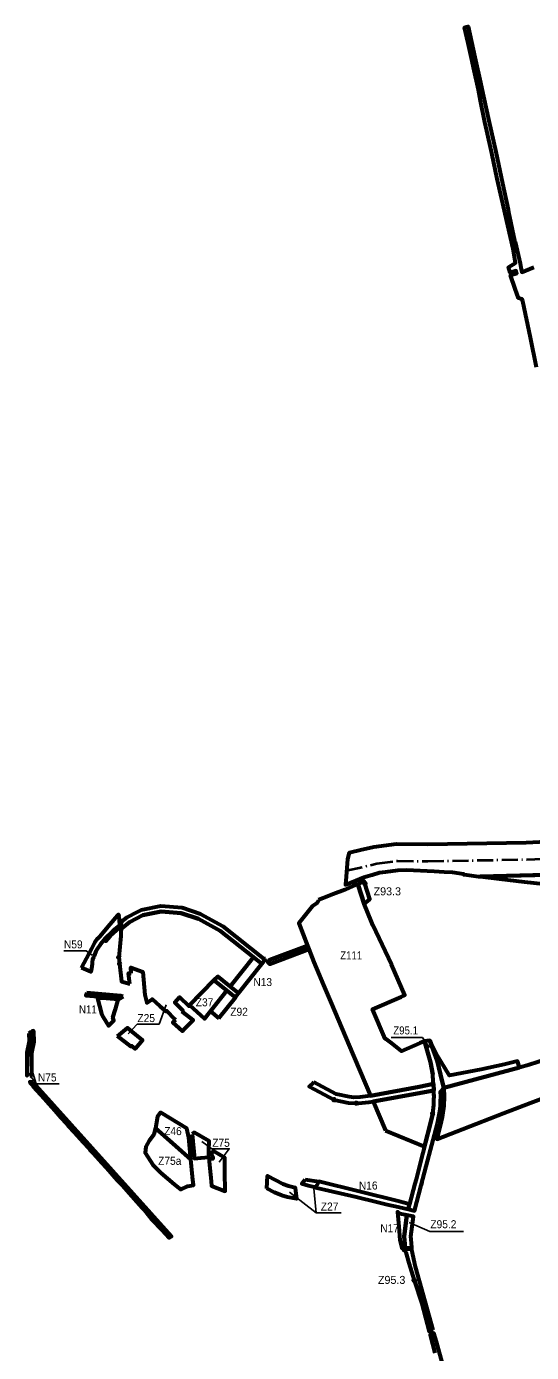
# Model space of a CAD drawing. Extents: x -650277 to -643422, y -1073980 to -1066720.
# Drawn here: x -650277 to -648765, y -1070696 to -1066720 of the extents above; entities that cross this region are included whole.
import ezdxf

# ---------------------------------------------------------------- set-up
doc = ezdxf.new("R2010")
doc.units = 0
doc.header["$LTSCALE"] = 9.6
doc.header["$PDMODE"] = 32
doc.header["$PDSIZE"] = 4.8
doc.linetypes.add('DOT_DASHED', pattern=[7.7, 5, -1.2, 0.3, -1.2])
for name, color, linetype, lineweight in [('1', 7, 'Continuous', 60), ('11', 7, 'Continuous', 60), ('12', 7, 'Continuous', 60), ('13', 7, 'Continuous', 60), ('15', 7, 'Continuous', 60), ('18', 7, 'Continuous', 60), ('24', 7, 'Continuous', 60), ('3', 7, 'Continuous', 60), ('40', 7, 'Continuous', 60), ('41', 7, 'Continuous', 60), ('42', 7, 'Continuous', 60), ('48', 7, 'Continuous', 60), ('60', 7, 'Continuous', 60), ('62', 7, 'DOT_DASHED', 40), ('63', 7, 'Continuous', 25), ('7', 7, 'Continuous', 60), ('9', 7, 'Continuous', 60)]:
    doc.layers.add(name, color=color, linetype=linetype, lineweight=lineweight)

msp = doc.modelspace()

# ---------------------------------------------------------------- linework, layer by layer
at = {"layer": '1'}
msp.add_line((-650000.59, -1069511.15), (-649998.5, -1069529.88), dxfattribs=at)
for points in [[(-649814.067, -1069377.972), (-649874.391, -1069373.859), (-649929.015, -1069384.784), (-649968.465, -1069405.189)], [(-649598.004, -1069510.814), (-649697.525, -1069431.522), (-649762.488, -1069395.854), (-649814.067, -1069377.972)], [(-649968.465, -1069405.189), (-649994.293, -1069425.949), (-649994.53, -1069447.61), (-650000.59, -1069511.15), (-650000.59, -1069511.15)], [(-649812.153, -1069672.884), (-649809.47, -1069670.13), (-649833.38, -1069646.08), (-649818.71, -1069630.64), (-649791.3, -1069657.21), (-649788.91, -1069654.4), (-649715.908, -1069579.804), (-649704.646, -1069568.296), (-649688.446, -1069581.203), (-649667.188, -1069598.14), (-649598.004, -1069510.814)], [(-649998.5, -1069529.88), (-649992.59, -1069582.88), (-649967.81, -1069590.74)], [(-649963.43, -1069557.91), (-649965.26, -1069541.51), (-649928.48, -1069554.57), (-649923.17, -1069623.14)], [(-649967.81, -1069590.74), (-649971.38, -1069558.79), (-649963.43, -1069557.91)], [(-649923.17, -1069623.14), (-649918.35, -1069643.45), (-649917.38, -1069647.56), (-649900.64, -1069636.78), (-649877.82, -1069656.83), (-649864.596, -1069668.455), (-649859.96, -1069672.53)], [(-649859.96, -1069672.53), (-649859.17, -1069673.22), (-649857.49, -1069671.46), (-649833.94, -1069695.24), (-649831.124, -1069698.083)], [(-649831.124, -1069698.083), (-649838.99, -1069706.15), (-649819.9, -1069723.61), (-649810.41, -1069732.28), (-649807.66, -1069729.46), (-649792.13, -1069713.65), (-649777.94, -1069699.2), (-649808.96, -1069675.34), (-649812.153, -1069672.884)]]:
    msp.add_lwpolyline(points, dxfattribs=at)
at = {"layer": '1', "lineweight": 25}
msp.add_lwpolyline([(-649946, -1069711), (-649880, -1069711), (-649859, -1069653)], dxfattribs=at)
at = {"layer": '1'}
for points in [[(-650004.59, -1069747.27), (-649974.86, -1069721.96), (-649966.52, -1069728.87), (-649929.38, -1069759.65), (-649951.56, -1069785.42), (-649963, -1069776.7), (-649965, -1069778.7)], [(-649557.21, -1070203.53), (-649555.44, -1070165.91), (-649532.57, -1070178.08), (-649509.72, -1070190.24), (-649492.67, -1070196.34), (-649472.6, -1070201.15), (-649472.43, -1070202.9), (-649469.176, -1070235.365), (-649496, -1070230), (-649513, -1070225), (-649535, -1070216)], [(-649442.63, -1070176.69), (-649402.29, -1070182.92), (-649404.2, -1070187.43), (-649412.2, -1070200.71), (-649433.3, -1070195.89), (-649453.27, -1070190.02), (-649446.19, -1070180.76)]]:
    msp.add_lwpolyline(points, close=True, dxfattribs=at)
for p in [(-650000.59, -1069511.15), (-649998.5, -1069529.88)]:
    msp.add_point(p, dxfattribs=at)
at = {"layer": '11'}
msp.add_lwpolyline([(-649788.91, -1069654.4), (-649744.517, -1069695.746), (-649677.124, -1069610.681), (-649715.908, -1069579.804)], close=True, dxfattribs=at)
at = {"layer": '12'}
for points in [[(-649891.21, -1070022.68), (-649832.007, -1070074.751), (-649784.87, -1070116.76), (-649791.31, -1070051.51), (-649797.45, -1070023.77), (-649876.31, -1069975.93), (-649884.59, -1069988.57)], [(-649891.21, -1070022.68), (-649895.45, -1070042.15), (-649910.34, -1070061.29), (-649919.55, -1070079.01), (-649922.3, -1070096.9), (-649898.55, -1070132.9), (-649874.94, -1070157.19), (-649835.28, -1070191.27), (-649815.33, -1070206.63), (-649794.37, -1070197.2), (-649777.29, -1070193.57), (-649779.75, -1070168.69), (-649784.87, -1070116.76)]]:
    msp.add_lwpolyline(points, close=True, dxfattribs=at)
at = {"layer": '13'}
msp.add_line((-649202.375, -1070030.469), (-649085.737, -1070078.201), dxfattribs=at)
for points in [[(-649057.868, -1069910.51), (-649239.635, -1069943.094), (-649202.375, -1070030.469)], [(-649085.737, -1070078.201), (-649066.487, -1070004.267), (-649061.139, -1069979.254), (-649061.138, -1069979.243)]]:
    msp.add_lwpolyline(points, dxfattribs=at)
msp.add_arc((-649347.129, -1069931.193), 290, 350.46253, 4.08974, dxfattribs=at)
msp.add_point((-649061.138, -1069979.243), dxfattribs=at)
at = {"layer": '15'}
msp.add_line((-649057.868, -1069910.51), (-649058.82, -1069890.548), dxfattribs=at)
for points in [[(-648749.97, -1067741.49), (-648767.84, -1067652.98), (-648791.68, -1067543.78), (-648792.97, -1067537.86), (-648804.08, -1067534.88), (-648813.94, -1067506.27), (-648827.86, -1067465.86), (-648809.65, -1067459.77), (-648809.97, -1067458.52), (-648811.21, -1067453.52), (-648811.4, -1067452.79), (-648829.54, -1067458.42), (-648834.01, -1067441.81), (-648812.91, -1067429.16), (-648820.39, -1067386.83), (-648844.16, -1067281.37), (-648845.94, -1067272.85), (-648867.82, -1067176.66), (-648884.26, -1067099.63), (-648899.1, -1067033.34), (-648905.06, -1067006.7), (-648917.76, -1066942.65), (-648924.32, -1066909.55), (-648936.7, -1066852.52), (-648944.75, -1066815.41), (-648955.15, -1066770.11), (-648965.39, -1066723.15), (-648959.88, -1066721.59), (-648954.86, -1066720.16), (-648935.19, -1066812.53), (-648918.27, -1066888.41), (-648914.11, -1066907.05), (-648893.02, -1067002.5), (-648872.31, -1067095.5), (-648851.87, -1067191.04), (-648835.29, -1067268.93), (-648833.66, -1067276.77), (-648816.06, -1067361.71), (-648813.81, -1067365.91), (-648799.58, -1067430.4), (-648796.8, -1067443.1), (-648795.88, -1067447.21), (-648794.7, -1067452.46), (-648793.71, -1067456.88), (-648757.97, -1067441.51)], [(-649561.17, -1069515.83), (-649566.951, -1069515.099), (-649688.625, -1069418.156), (-649755.971, -1069381.179), (-649810.846, -1069362.154), (-649875.434, -1069357.751), (-649934.363, -1069369.537), (-649945.397, -1069375.277), (-649977.239, -1069391.714), (-649994.329, -1069405.451)], [(-649994.293, -1069425.949), (-649968.465, -1069405.189), (-649929.015, -1069384.784), (-649874.391, -1069373.859)], [(-649874.391, -1069373.859), (-649814.067, -1069377.972), (-649762.488, -1069395.854), (-649697.525, -1069431.522), (-649598.004, -1069510.814), (-649572.972, -1069530.758)], [(-649994.329, -1069405.451), (-649994.329, -1069405.451), (-649994.293, -1069425.949), (-649994.293, -1069425.949)], [(-649572.972, -1069530.758), (-649561.91, -1069516.78), (-649561.17, -1069515.83)], [(-650096.627, -1069617.746), (-650099.55, -1069625.53), (-650002.39, -1069633.65)], [(-649987.49, -1069628.6), (-649994.913, -1069626.246), (-650096.627, -1069617.746)], [(-650002.39, -1069633.65), (-650002.65, -1069637.14), (-649987.49, -1069628.6)], [(-649417.234, -1069885.193), (-649418.94, -1069887.36), (-649430.515, -1069898.514), (-649356.458, -1069937.945)], [(-649246.81, -1069926.27), (-649278.492, -1069930.573), (-649296.851, -1069931.092), (-649310.738, -1069929.342), (-649350.222, -1069920.873), (-649417.234, -1069885.193)], [(-649058.82, -1069890.548), (-649101.89, -1069898.73), (-649246.81, -1069926.27)], [(-649356.458, -1069937.945), (-649312.646, -1069947.342), (-649289.95, -1069948.146)], [(-649289.95, -1069948.146), (-649282.437, -1069948.342), (-649251.805, -1069945.276), (-649239.635, -1069943.094), (-649057.868, -1069910.51)]]:
    msp.add_lwpolyline(points, dxfattribs=at)
for points in [[(-650025.31, -1069446.49), (-649998.512, -1069422.926), (-649999.01, -1069415.628), (-650018.873, -1069431.749), (-650043.521, -1069455.69), (-650045.72, -1069459.1), (-650040.012, -1069461.999)], [(-649547.733, -1069530.185), (-649431.761, -1069486.57), (-649435.578, -1069476.772), (-649550.53, -1069519.68), (-649554.83, -1069525), (-649551.32, -1069528.49), (-649549.69, -1069530.14), (-649548.881, -1069530.963)], [(-649677.124, -1069610.681), (-649651.846, -1069630.82), (-649641.978, -1069618.226), (-649667.188, -1069598.14), (-649688.446, -1069581.203), (-649704.646, -1069568.296), (-649715.908, -1069579.804)], [(-648800.85, -1069841.52), (-648806.946, -1069821.79), (-648846.924, -1069832.58), (-648916.03, -1069847.12), (-649010.55, -1069865.09), (-649049.22, -1069801.23), (-649069.4, -1069760.67), (-649048, -1069820), (-649032.928, -1069882.782), (-649028.017, -1069902.109)]]:
    msp.add_lwpolyline(points, close=True, dxfattribs=at)
for p in [(-649994.329, -1069405.451), (-649994.293, -1069425.949), (-649356.458, -1069937.945), (-649289.95, -1069948.146)]:
    msp.add_point(p, dxfattribs=at)
at = {"layer": '18'}
for points in [[(-649781.53, -1070041.2), (-649774.45, -1070113.92), (-649754.82, -1070111.89), (-649731.12, -1070109.96), (-649730.96, -1070094.91), (-649730.89, -1070088.96), (-649730.6, -1070061.98), (-649774.73, -1070035.58)], [(-649730.57, -1070115.76), (-649730, -1070122.01), (-649726.22, -1070162.75), (-649725.49, -1070170.64), (-649723.17, -1070195.81), (-649682.04, -1070211.58), (-649683.12, -1070154.14), (-649682.98, -1070132.1), (-649683.57, -1070112.05), (-649717.72, -1070091.61), (-649718.71, -1070093.35), (-649724.36, -1070099.03), (-649719.69, -1070108.94), (-649719.24, -1070114.87)]]:
    msp.add_lwpolyline(points, close=True, dxfattribs=at)
at = {"layer": '24'}
for points in [[(-649321.69, -1069307.61), (-649324.3, -1069308.59), (-649359.48, -1069321.82), (-649389.4, -1069333.35), (-649396.52, -1069336.09), (-649403.92, -1069338.26)], [(-649283.702, -1069294.132), (-649284.695, -1069291.033), (-649300.133, -1069297.95), (-649321.69, -1069307.61)], [(-649060.897, -1069861.994), (-649068, -1069825.147), (-649085.41, -1069762.44), (-649085.41, -1069762.44), (-649099.75, -1069768.575), (-649154.76, -1069792.11), (-649184.05, -1069768.45), (-649200.64, -1069756.53), (-649202.99, -1069754.99), (-649241.11, -1069665.9), (-649155.082, -1069629.097), (-649144.57, -1069624.6), (-649184.1, -1069532.2), (-649240.202, -1069414.528), (-649244.08, -1069404.753), (-649265.774, -1069350.068), (-649283.702, -1069294.132)], [(-649403.92, -1069338.26), (-649403.03, -1069340.66), (-649408.81, -1069349.89), (-649422.19, -1069357.99), (-649462.25, -1069408.32), (-649435.578, -1069476.772), (-649431.761, -1069486.57)], [(-649431.761, -1069486.57), (-649416.52, -1069525.68), (-649409.355, -1069544.517), (-649388.438, -1069594.296), (-649379.32, -1069615.71), (-649364.44, -1069650.55), (-649312.03, -1069773.33)], [(-649312.03, -1069773.33), (-649246.81, -1069926.27), (-649101.89, -1069898.73), (-649058.82, -1069890.548)]]:
    msp.add_lwpolyline(points, dxfattribs=at)
msp.add_arc((-649649.71, -1069919.176), 591.583, 2.77379, 5.54687, dxfattribs=at)
at = {"layer": '3'}
msp.add_lwpolyline([(-648722.24, -1069817.54), (-648772.48, -1069832.83), (-648800.85, -1069841.52), (-649028.017, -1069902.109), (-649027.135, -1069928.902), (-649027.953, -1069955.702), (-649032.644, -1069990.371), (-649037.411, -1070011.659), (-649048.918, -1070055.852), (-648931.057, -1070010.171), (-648849.532, -1069978.559), (-648767.83, -1069946.87), (-648562.242, -1069870.301)], dxfattribs=at)
at = {"layer": '40'}
for points in [[(-649667.188, -1069598.14), (-649641.978, -1069618.226), (-649572.972, -1069530.758), (-649598.004, -1069510.814)], [(-650002.65, -1069637.14), (-650050.26, -1069633.65), (-650064.77, -1069633.06), (-650052.88, -1069679.49), (-650047.45, -1069690.69), (-650031.64, -1069715.9), (-650015.53, -1069700.21), (-650018.31, -1069690.89), (-650011.15, -1069665.82)], [(-649160.748, -1070243.413), (-649402.29, -1070182.92), (-649404.2, -1070187.43), (-649412.2, -1070200.71), (-649412.2, -1070200.71), (-649408.24, -1070201.62), (-649372.69, -1070209.74), (-649289.83, -1070229.16), (-649229.8, -1070243.94), (-649197.55, -1070251.65), (-649164.91, -1070258.55), (-649160.54, -1070259.96), (-649134.294, -1070266.095), (-649130.712, -1070250.935)]]:
    msp.add_lwpolyline(points, close=True, dxfattribs=at)
at = {"layer": '41'}
msp.add_lwpolyline([(-649812.153, -1069672.884), (-649808.96, -1069675.34), (-649777.94, -1069699.2), (-649792.13, -1069713.65), (-649807.66, -1069729.46), (-649810.41, -1069732.28), (-649819.9, -1069723.61), (-649838.99, -1069706.15), (-649831.124, -1069698.083)], dxfattribs=at)
at = {"layer": '42'}
msp.add_lwpolyline([(-650112.18, -1069542.11), (-650081.29, -1069484.35), (-650072.5, -1069466.44), (-650063.12, -1069453.54), (-650062.17, -1069454.05), (-650060.29, -1069451.7), (-650057.49, -1069448.18), (-650026.33, -1069411.47), (-650003.73, -1069384.71), (-650002.11, -1069382.8), (-650001.13, -1069388.13), (-649999.95, -1069397.98), (-649999.01, -1069415.628), (-650018.873, -1069431.749), (-650043.521, -1069455.69), (-650045.72, -1069459.1), (-650055.612, -1069471.639), (-650066.897, -1069487.541), (-650069.369, -1069492.132), (-650074.75, -1069506.133), (-650076.365, -1069510.333), (-650079.264, -1069517.874), (-650080.302, -1069525.418), (-650080.802, -1069530.768), (-650082.963, -1069544.736), (-650084.345, -1069554.773)], close=True, dxfattribs=at)
at = {"layer": '48'}
for points in [[(-650270.059, -1069739.232), (-650269.449, -1069762.714), (-650276.214, -1069796.532), (-650275.76, -1069865.474), (-650274.95, -1069865.62), (-650273.87, -1069809.74), (-650273.78, -1069805.2), (-650273.58, -1069794.48), (-650270.15, -1069778.65), (-650267.22, -1069765.1), (-650265.37, -1069741.61), (-650264.91, -1069735.69)], [(-650260.645, -1069868.536), (-650260.748, -1069867.327), (-650261.204, -1069797.969), (-650254.411, -1069764.006), (-650255.21, -1069733.253), (-650255.716, -1069731.162), (-650259.97, -1069732.29), (-650258.74, -1069750.62), (-650257.77, -1069765.2), (-650262.93, -1069794.84), (-650262.77, -1069805.54), (-650262.7, -1069809.89), (-650261.8, -1069868.33)], [(-650257.713, -1069885.547), (-650266.89, -1069883.7), (-650266.68, -1069886.78), (-650262.64, -1069891.57), (-650257.16, -1069898.07), (-650224.71, -1069934.41), (-650209.51, -1069951.43), (-650192.51, -1069970.47), (-650174.3, -1069990.86), (-650157.87, -1070009.26), (-650151.03, -1070016.84), (-650134.26, -1070035.45), (-650106.76, -1070065.96), (-650091.89, -1070082.46), (-650087.18, -1070087.68), (-650076.72, -1070099.29), (-650051.33, -1070127.45), (-650037.78, -1070142.48), (-650018.41, -1070163.97), (-650005.3, -1070178.51), (-649990.95, -1070194.43), (-649977.05, -1070209.85), (-649946.39, -1070243.87), (-649930.46, -1070261.54), (-649924.15, -1070268.55), (-649913.03, -1070282.44), (-649901.59, -1070296.73), (-649871.28, -1070329.01), (-649850.04, -1070351.64), (-649843.513, -1070347.685)]]:
    msp.add_lwpolyline(points, close=True, dxfattribs=at)
at = {"layer": '60'}
for p, q in [((-649058.858, -1069889.759), (-649057.868, -1069910.51)), ((-649057.134, -1069932.873), (-649057.868, -1069910.51)), ((-649146.163, -1070347.543), (-649145.424, -1070357.637))]:
    msp.add_line(p, q, dxfattribs=at)
for points in [[(-648721.315, -1069164.952), (-648781.015, -1069167.44), (-649076.02, -1069172.683), (-649169.781, -1069171.432), (-649237.512, -1069180.731), (-649277.021, -1069189.913), (-649306.455, -1069196.754), (-649311.633, -1069197.958), (-649316.47, -1069216.91), (-649321.32, -1069281.47), (-649322.09, -1069291.73), (-649322.22, -1069293.54), (-649319.72, -1069292.47), (-649267.5, -1069270.41), (-649242.5, -1069263.3), (-649220.18, -1069257.03), (-649202.63, -1069254.4), (-649165.62, -1069249.43), (-649139.63, -1069248.73), (-649056.95, -1069252.55), (-649026.955, -1069254.366), (-649001.3, -1069255.92), (-648968.49, -1069260.36), (-648968.05, -1069263.06), (-648965.8, -1069262.75), (-648937.91, -1069266.51), (-648924.13, -1069268.21), (-648918.889, -1069268.875), (-648673.267, -1069262.895)], [(-649061.138, -1069979.243), (-649061.138, -1069979.243), (-649061.139, -1069979.254), (-649066.487, -1070004.267), (-649098.65, -1070127.795), (-649110.925, -1070177.113), (-649114.174, -1070189.816), (-649130.712, -1070250.935), (-649134.294, -1070266.095), (-649115.159, -1070270.568), (-649095.152, -1070193.731), (-649093.095, -1070186.132), (-649095.152, -1070193.731), (-649080.924, -1070137.409), (-649080.38, -1070136.996), (-649047.131, -1070009.304), (-649042.468, -1069988.477), (-649042.468, -1069988.477), (-649039.966, -1069973.035), (-649037.98, -1069956.626), (-649037.322, -1069942.129), (-649037.137, -1069928.996), (-649037.665, -1069912.977), (-649028.017, -1069902.109), (-649032.928, -1069882.782), (-649048, -1069820), (-649069.4, -1069760.67), (-649085.41, -1069762.44), (-649068, -1069825.147), (-649060.897, -1069861.994)], [(-649138.43, -1070283.6), (-649146.163, -1070347.543), (-649146.163, -1070347.543)], [(-649125.503, -1070355.837), (-649126.069, -1070348.097), (-649118.257, -1070287.455), (-649138.43, -1070283.6)], [(-649059.951, -1070628.223), (-649112.14, -1070439.152), (-649123.138, -1070388.16), (-649123.385, -1070384.775), (-649145.73, -1070387.91)], [(-649145.424, -1070357.637), (-649143.633, -1070382.123), (-649123.693, -1070380.572), (-649125.503, -1070355.837)], [(-649145.73, -1070387.91), (-649141.48, -1070394.84), (-649132.07, -1070426.81), (-649116.56, -1070479.19)], [(-649116.56, -1070479.19), (-649093.2, -1070549.1), (-649071.33, -1070632.6), (-649059.951, -1070628.223)], [(-649025.129, -1070754.377), (-649047.11, -1070674.743), (-649050.081, -1070663.981), (-649057.338, -1070637.689), (-649068.65, -1070642.23), (-649068.65, -1070642.23), (-649054.31, -1070696.44)]]:
    msp.add_lwpolyline(points, dxfattribs=at)
for points in [[(-648730.66, -1069290.43), (-648656.242, -1069297.116), (-648673.267, -1069262.895), (-648761.189, -1069265.035), (-648918.889, -1069268.875), (-648909.86, -1069270.02), (-648861.49, -1069275.34), (-648785.92, -1069284.2), (-648730.66, -1069290.43)], [(-649701.211, -1069692.826), (-649651.773, -1069630.879), (-649677.124, -1069610.681), (-649726.033, -1069672.415)]]:
    msp.add_lwpolyline(points, close=True, dxfattribs=at)
for centre, radius, start, end in [((-649633.43, -1069918.001), 575.266, 2.81398, 5.58706), ((-649347.129, -1069931.193), 290, 350.46253, 4.08974), ((-649347.129, -1069931.193), 290, 359.66809, 4.08974)]:
    msp.add_arc(centre, radius, start, end, dxfattribs=at)
for p in [(-649145.73, -1070387.91), (-649116.56, -1070479.19)]:
    msp.add_point(p, dxfattribs=at)
at = {"layer": '62'}
msp.add_lwpolyline([(-649319.032, -1069251.01), (-649228.433, -1069229.954), (-649166.697, -1069221.478), (-649075.909, -1069222.689), (-648779.53, -1069217.422), (-648667.088, -1069212.737)], dxfattribs=at)
at = {"layer": '63'}
for p, q in [((-649973, -1069740), (-649946, -1069711)), ((-650248, -1069890), (-650277, -1069850)), ((-650248, -1069890), (-650261, -1069847)), ((-649410, -1070277), (-649417.769, -1070193.978))]:
    msp.add_line(p, q, dxfattribs=at)
for points in [[(-650165, -1069491), (-650099, -1069491), (-650081, -1069504)], [(-649185, -1069751), (-649092, -1069751), (-649071, -1069781)], [(-650243, -1069909), (-650248, -1069890), (-650179, -1069890)], [(-649752, -1070063), (-649722, -1070085), (-649670, -1070085), (-649700, -1070125)], [(-649335, -1070277), (-649410, -1070277), (-649490, -1070215)], [(-648969, -1070333), (-649070, -1070333), (-649132, -1070306)]]:
    msp.add_lwpolyline(points, dxfattribs=at)
at = {"layer": '7'}
msp.add_lwpolyline([(-649138.43, -1070283.6), (-649159.78, -1070279.52), (-649166.86, -1070273.48), (-649162.91, -1070317.47), (-649159.19, -1070358.82), (-649153.64, -1070382.9), (-649148.23, -1070382.48), (-649143.633, -1070382.123), (-649146.163, -1070347.543)], close=True, dxfattribs=at)
at = {"layer": '9'}
msp.add_line((-649283.702, -1069294.132), (-649265.774, -1069350.068), dxfattribs=at)
for points in [[(-649264.156, -1069289.589), (-649266.331, -1069282.804), (-649284.695, -1069291.033), (-649283.702, -1069294.132)], [(-649265.774, -1069350.068), (-649249.069, -1069336.66), (-649264.156, -1069289.589)]]:
    msp.add_lwpolyline(points, dxfattribs=at)
for p in [(-649283.702, -1069294.132), (-649264.156, -1069289.589)]:
    msp.add_point(p, dxfattribs=at)

# ---------------------------------------------------------------- texts
at = {"layer": '1', "width": 0.95}
msp.add_text('Z25', height=24, dxfattribs=at).set_placement((-649945, -1069705))
at = {"layer": '63'}
for s, p in [('Z93.3', (-649238, -1069325)), ('Z95.3', (-649225, -1070490))]:
    msp.add_text(s, height=24, dxfattribs=at).set_placement(p)
for s, width, p in [('N59', 0.95, (-650165, -1069484)), ('Z111', 0.9, (-649338, -1069517)), ('N13', 0.95, (-649598, -1069597)), ('N11', 0.9, (-650120, -1069679)), ('Z37', 0.95, (-649770.387, -1069657.603)), ('Z92', 0.95, (-649667, -1069686)), ('Z95.1', 0.9, (-649179, -1069742)), ('N75', 0.95, (-650243, -1069883)), ('Z46', 0.95, (-649865, -1070044)), ('Z75', 0.95, (-649721, -1070079)), ('Z75a', 0.95, (-649883, -1070133)), ('N16', 0.95, (-649282, -1070207)), ('Z27', 0.95, (-649396, -1070270)), ('Z95.2', 0.95, (-649068, -1070323)), ('N17', 0.95, (-649218, -1070335))]:
    msp.add_text(s, height=24, dxfattribs=dict(at, width=width)).set_placement(p)

doc.saveas('drawing.dxf')
